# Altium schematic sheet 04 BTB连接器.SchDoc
size 420 x 297 mm
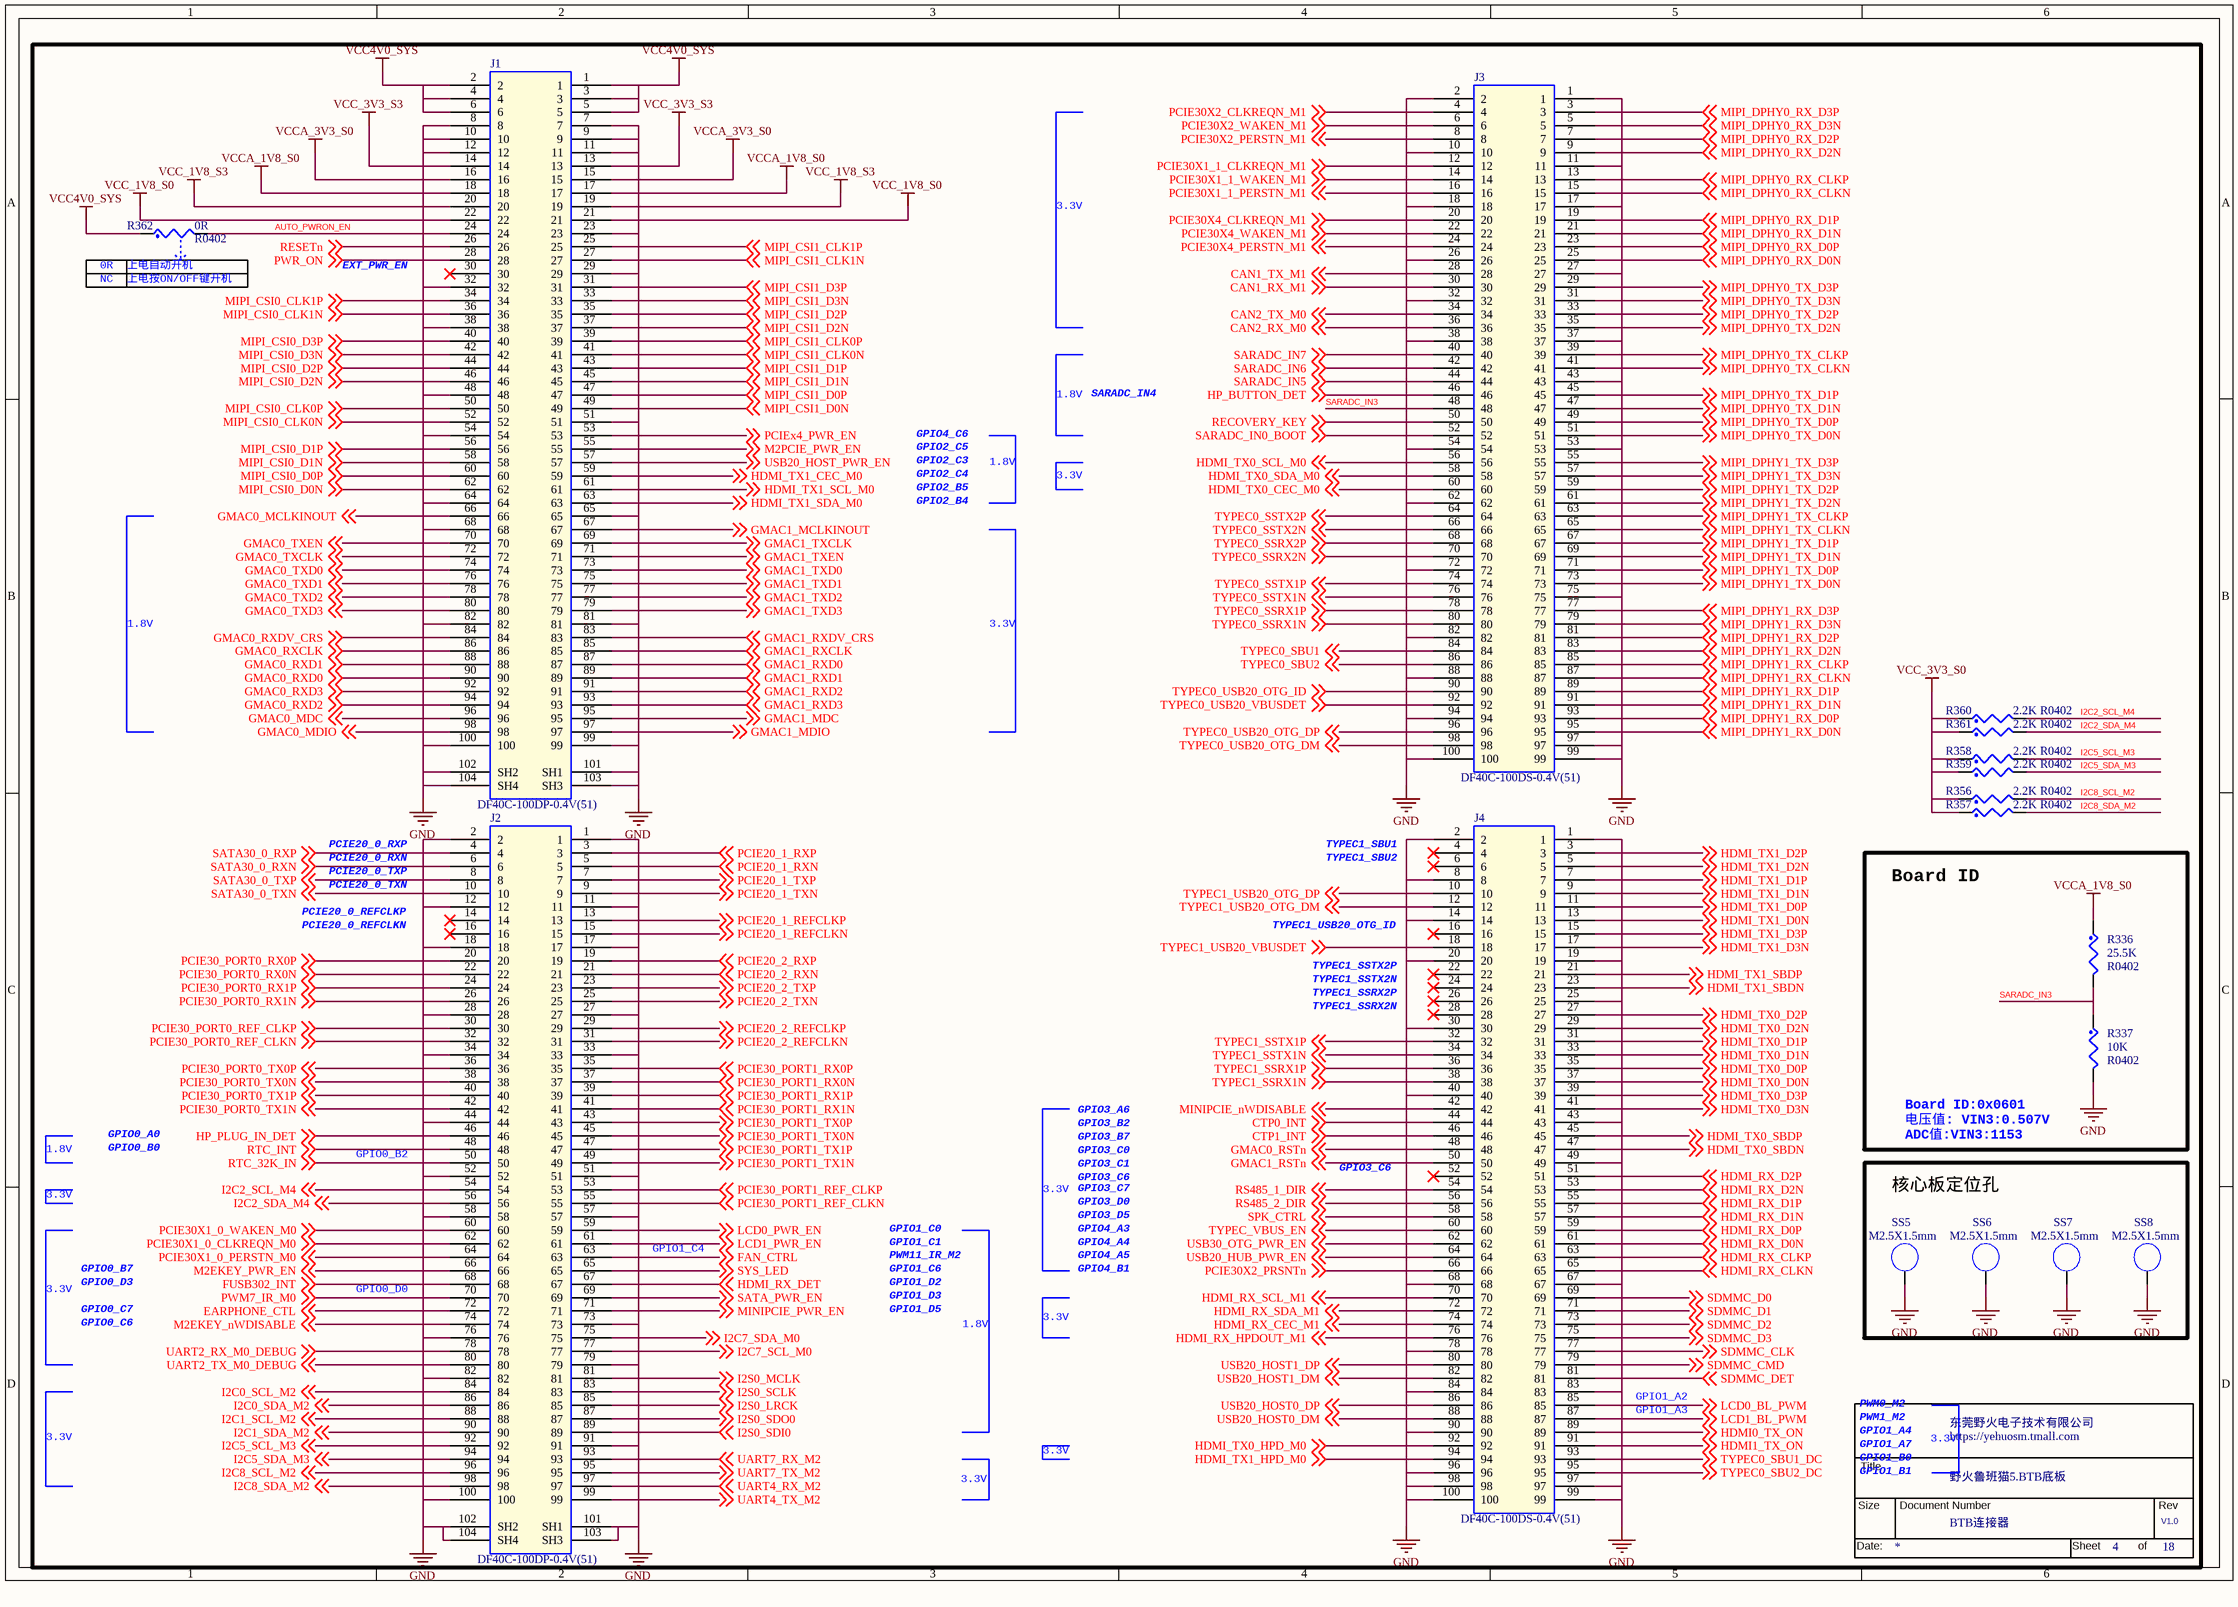
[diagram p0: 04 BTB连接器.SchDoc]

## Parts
*  Doc: BTB连接器  RevCode: V1.0  Title: 野火鲁班猫5.BTB底板  OrgName: 东莞野火电子技术有限公司  Page Number: 4  Page Count: 18  (hidden comment: TitleBlock_YHSCH)  (graphical)
J1  DF40C-100DP-0.4V(51)  [DF40C-100DP-0P4V]
J2  DF40C-100DP-0.4V(51)  [DF40C-100DP-0P4V]
J3  DF40C-100DS-0.4V(51)  [DF40HC-100DS-0P4V]
J4  DF40C-100DS-0.4V(51)  [DF40HC-100DS-0P4V]
R336  25.5K  [R0402]
R337  10K  [R0402]
R356  2.2K  [R0402]
R357  2.2K  [R0402]
R358  2.2K  [R0402]
R359  2.2K  [R0402]
R360  2.2K  [R0402]
R361  2.2K  [R0402]
R362  0R  [R0402]
SS5  M2.5X1.5mm  [SMTSO-M2r5]
SS6  M2.5X1.5mm  [SMTSO-M2r5]
SS7  M2.5X1.5mm  [SMTSO-M2r5]
SS8  M2.5X1.5mm  [SMTSO-M2r5]

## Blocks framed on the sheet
Board ID: R336 R337
核心板定位孔: SS5-SS8

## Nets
GND: J1.7 J1.8 J1.9 J1.10 J1.11 J1.12 J1.23 J1.29 J1.32 J1.38 J1.48 J1.51 J1.54 J1.64 J1.65 J1.68 J1.81 J1.82 J1.99 J1.100 J1.101(SH1) J1.102(SH2) J1.103(SH3) J1.104(SH4) J2.1 J2.2 J2.11 J2.12 J2.17 J2.18 J2.27 J2.28 J2.33 J2.34 J2.44 J2.51 J2.52 J2.57 J2.58 J2.73 J2.76 J2.79 J2.82 J2.91 J2.100 J2.101(SH1) J2.102(SH2) J2.103(SH3) J2.104(SH4) J3.1 J3.2 J3.10 J3.11 J3.17 J3.18 J3.26 J3.27 J3.32 J3.37 J3.38 J3.43 J3.53 J3.54 J3.62 J3.72 J3.75 J3.82 J3.88 J3.94 J3.97 J3.99 J3.100 J4.1 J4.2 J4.8 J4.14 J4.19 J4.20 J4.25 J4.30 J4.40 J4.43 J4.49 J4.67 J4.68 J4.78 J4.83 J4.84 J4.90 J4.96 J4.97 J4.98 J4.99 J4.100 R337.2 SS5.1(NC_1) SS6.1(NC_1) SS7.1(NC_1) SS8.1(NC_1)
VCC4V0_SYS: J1.1 J1.2 J1.3 J1.4 J1.5 J1.6 R362.1
VCC_1V8_S0: J1.21 J1.22
VCC_1V8_S3: J1.19 J1.20
VCC_3V3_S0: R356.1 R357.1 R358.1 R359.1 R360.1 R361.1
VCC_3V3_S3: J1.13 J1.14
VCCA_1V8_S0: J1.17 J1.18 R336.1
VCCA_3V3_S0: J1.15 J1.16
AUTO_PWRON_EN: J1.24 R362.2
CAN1_RX_M1: J3.30 ; off-sheet CAN1_RX_M1
CAN1_TX_M1: J3.28 ; off-sheet CAN1_TX_M1
CAN2_RX_M0: J3.36 ; off-sheet CAN2_RX_M0
CAN2_TX_M0: J3.34 ; off-sheet CAN2_TX_M0
CTP0_INT: J4.44 ; off-sheet CTP0_INT
CTP1_INT: J4.46 ; off-sheet CTP1_INT
EARPHONE_CTL: J2.72 ; off-sheet EARPHONE_CTL
FAN_CTRL: J2.63 ; off-sheet FAN_CTRL
FUSB302_INT: J2.68 ; off-sheet FUSB302_INT
GMAC0_MCLKINOUT: J1.66 ; off-sheet GMAC0_MCLKINOUT
GMAC0_MDC: J1.96 ; off-sheet GMAC0_MDC
GMAC0_MDIO: J1.98 ; off-sheet GMAC0_MDIO
GMAC0_RSTn: J4.48 ; off-sheet GMAC0_RSTn
GMAC0_RXCLK: J1.86 ; off-sheet GMAC0_RXCLK
GMAC0_RXD0: J1.90 ; off-sheet GMAC0_RXD0
GMAC0_RXD1: J1.88 ; off-sheet GMAC0_RXD1
GMAC0_RXD2: J1.94 ; off-sheet GMAC0_RXD2
GMAC0_RXD3: J1.92 ; off-sheet GMAC0_RXD3
GMAC0_RXDV_CRS: J1.84 ; off-sheet GMAC0_RXDV_CRS
GMAC0_TXCLK: J1.72 ; off-sheet GMAC0_TXCLK
GMAC0_TXD0: J1.74 ; off-sheet GMAC0_TXD0
GMAC0_TXD1: J1.76 ; off-sheet GMAC0_TXD1
GMAC0_TXD2: J1.78 ; off-sheet GMAC0_TXD2
GMAC0_TXD3: J1.80 ; off-sheet GMAC0_TXD3
GMAC0_TXEN: J1.70 ; off-sheet GMAC0_TXEN
GMAC1_MCLKINOUT: J1.67 ; off-sheet GMAC1_MCLKINOUT
GMAC1_MDC: J1.95 ; off-sheet GMAC1_MDC
GMAC1_MDIO: J1.97 ; off-sheet GMAC1_MDIO
GMAC1_RSTn: J4.50 ; off-sheet GMAC1_RSTn
GMAC1_RXCLK: J1.85 ; off-sheet GMAC1_RXCLK
GMAC1_RXD0: J1.87 ; off-sheet GMAC1_RXD0
GMAC1_RXD1: J1.89 ; off-sheet GMAC1_RXD1
GMAC1_RXD2: J1.91 ; off-sheet GMAC1_RXD2
GMAC1_RXD3: J1.93 ; off-sheet GMAC1_RXD3
GMAC1_RXDV_CRS: J1.83 ; off-sheet GMAC1_RXDV_CRS
GMAC1_TXCLK: J1.69 ; off-sheet GMAC1_TXCLK
GMAC1_TXD0: J1.73 ; off-sheet GMAC1_TXD0
GMAC1_TXD1: J1.75 ; off-sheet GMAC1_TXD1
GMAC1_TXD2: J1.77 ; off-sheet GMAC1_TXD2
GMAC1_TXD3: J1.79 ; off-sheet GMAC1_TXD3
GMAC1_TXEN: J1.71 ; off-sheet GMAC1_TXEN
HDMI0_TX_ON: J4.89 ; off-sheet HDMI0_TX_ON
HDMI1_TX_ON: J4.91 ; off-sheet HDMI1_TX_ON
HDMI_RX_CEC_M1: J4.74 ; off-sheet HDMI_RX_CEC_M1
HDMI_RX_CLKN: J4.65 ; off-sheet HDMI_RX_CLKN
HDMI_RX_CLKP: J4.63 ; off-sheet HDMI_RX_CLKP
HDMI_RX_D0N: J4.61 ; off-sheet HDMI_RX_D0N
HDMI_RX_D0P: J4.59 ; off-sheet HDMI_RX_D0P
HDMI_RX_D1N: J4.57 ; off-sheet HDMI_RX_D1N
HDMI_RX_D1P: J4.55 ; off-sheet HDMI_RX_D1P
HDMI_RX_D2N: J4.53 ; off-sheet HDMI_RX_D2N
HDMI_RX_D2P: J4.51 ; off-sheet HDMI_RX_D2P
HDMI_RX_DET: J2.67 ; off-sheet HDMI_RX_DET
HDMI_RX_HPDOUT_M1: J4.76 ; off-sheet HDMI_RX_HPDOUT_M1
HDMI_RX_SCL_M1: J4.70 ; off-sheet HDMI_RX_SCL_M1
HDMI_RX_SDA_M1: J4.72 ; off-sheet HDMI_RX_SDA_M1
HDMI_TX0_CEC_M0: J3.60 ; off-sheet HDMI_TX0_CEC_M0
HDMI_TX0_D0N: J4.37 ; off-sheet HDMI_TX0_D0N
HDMI_TX0_D0P: J4.35 ; off-sheet HDMI_TX0_D0P
HDMI_TX0_D1N: J4.33 ; off-sheet HDMI_TX0_D1N
HDMI_TX0_D1P: J4.31 ; off-sheet HDMI_TX0_D1P
HDMI_TX0_D2N: J4.29 ; off-sheet HDMI_TX0_D2N
HDMI_TX0_D2P: J4.27 ; off-sheet HDMI_TX0_D2P
HDMI_TX0_D3N: J4.41 ; off-sheet HDMI_TX0_D3N
HDMI_TX0_D3P: J4.39 ; off-sheet HDMI_TX0_D3P
HDMI_TX0_HPD_M0: J4.92 ; off-sheet HDMI_TX0_HPD_M0
HDMI_TX0_SBDN: J4.47 ; off-sheet HDMI_TX0_SBDN
HDMI_TX0_SBDP: J4.45 ; off-sheet HDMI_TX0_SBDP
HDMI_TX0_SCL_M0: J3.56 ; off-sheet HDMI_TX0_SCL_M0
HDMI_TX0_SDA_M0: J3.58 ; off-sheet HDMI_TX0_SDA_M0
HDMI_TX1_CEC_M0: J1.59 ; off-sheet HDMI_TX1_CEC_M0
HDMI_TX1_D0N: J4.13 ; off-sheet HDMI_TX1_D0N
HDMI_TX1_D0P: J4.11 ; off-sheet HDMI_TX1_D0P
HDMI_TX1_D1N: J4.9 ; off-sheet HDMI_TX1_D1N
HDMI_TX1_D1P: J4.7 ; off-sheet HDMI_TX1_D1P
HDMI_TX1_D2N: J4.5 ; off-sheet HDMI_TX1_D2N
HDMI_TX1_D2P: J4.3 ; off-sheet HDMI_TX1_D2P
HDMI_TX1_D3N: J4.17 ; off-sheet HDMI_TX1_D3N
HDMI_TX1_D3P: J4.15 ; off-sheet HDMI_TX1_D3P
HDMI_TX1_HPD_M0: J4.94 ; off-sheet HDMI_TX1_HPD_M0
HDMI_TX1_SBDN: J4.23 ; off-sheet HDMI_TX1_SBDN
HDMI_TX1_SBDP: J4.21 ; off-sheet HDMI_TX1_SBDP
HDMI_TX1_SCL_M0: J1.61 ; off-sheet HDMI_TX1_SCL_M0
HDMI_TX1_SDA_M0: J1.63 ; off-sheet HDMI_TX1_SDA_M0
HP_BUTTON_DET: J3.46 ; off-sheet HP_BUTTON_DET
HP_PLUG_IN_DET: J2.46 ; off-sheet HP_PLUG_IN_DET
I2C0_SCL_M2: J2.84 ; off-sheet I2C0_SCL_M2
I2C0_SDA_M2: J2.86 ; off-sheet I2C0_SDA_M2
I2C1_SCL_M2: J2.88 ; off-sheet I2C1_SCL_M2
I2C1_SDA_M2: J2.90 ; off-sheet I2C1_SDA_M2
I2C2_SCL_M4: J2.54 R360.2 ; off-sheet I2C2_SCL_M4
I2C2_SDA_M4: J2.56 R361.2 ; off-sheet I2C2_SDA_M4
I2C5_SCL_M3: J2.92 R358.2 ; off-sheet I2C5_SCL_M3
I2C5_SDA_M3: J2.94 R359.2 ; off-sheet I2C5_SDA_M3
I2C7_SCL_M0: J2.77 ; off-sheet I2C7_SCL_M0
I2C7_SDA_M0: J2.75 ; off-sheet I2C7_SDA_M0
I2C8_SCL_M2: J2.96 R356.2 ; off-sheet I2C8_SCL_M2
I2C8_SDA_M2: J2.98 R357.2 ; off-sheet I2C8_SDA_M2
I2S0_LRCK: J2.85 ; off-sheet I2S0_LRCK
I2S0_MCLK: J2.81 ; off-sheet I2S0_MCLK
I2S0_SCLK: J2.83 ; off-sheet I2S0_SCLK
I2S0_SDI0: J2.89 ; off-sheet I2S0_SDI0
I2S0_SDO0: J2.87 ; off-sheet I2S0_SDO0
LCD0_BL_PWM: J4.85 ; off-sheet LCD0_BL_PWM
LCD0_PWR_EN: J2.59 ; off-sheet LCD0_PWR_EN
LCD1_BL_PWM: J4.87 ; off-sheet LCD1_BL_PWM
LCD1_PWR_EN: J2.61 ; off-sheet LCD1_PWR_EN
M2EKEY_nWDISABLE: J2.74 ; off-sheet M2EKEY_nWDISABLE
M2EKEY_PWR_EN: J2.66 ; off-sheet M2EKEY_PWR_EN
M2PCIE_PWR_EN: J1.55 ; off-sheet M2PCIE_PWR_EN
MINIPCIE_nWDISABLE: J4.42 ; off-sheet MINIPCIE_nWDISABLE
MINIPCIE_PWR_EN: J2.71 ; off-sheet MINIPCIE_PWR_EN
MIPI_CSI0_CLK0N: J1.52 ; off-sheet MIPI_CSI0_CLK0N
MIPI_CSI0_CLK0P: J1.50 ; off-sheet MIPI_CSI0_CLK0P
MIPI_CSI0_CLK1N: J1.36 ; off-sheet MIPI_CSI0_CLK1N
MIPI_CSI0_CLK1P: J1.34 ; off-sheet MIPI_CSI0_CLK1P
MIPI_CSI0_D0N: J1.62 ; off-sheet MIPI_CSI0_D0N
MIPI_CSI0_D0P: J1.60 ; off-sheet MIPI_CSI0_D0P
MIPI_CSI0_D1N: J1.58 ; off-sheet MIPI_CSI0_D1N
MIPI_CSI0_D1P: J1.56 ; off-sheet MIPI_CSI0_D1P
MIPI_CSI0_D2N: J1.46 ; off-sheet MIPI_CSI0_D2N
MIPI_CSI0_D2P: J1.44 ; off-sheet MIPI_CSI0_D2P
MIPI_CSI0_D3N: J1.42 ; off-sheet MIPI_CSI0_D3N
MIPI_CSI0_D3P: J1.40 ; off-sheet MIPI_CSI0_D3P
MIPI_CSI1_CLK0N: J1.41 ; off-sheet MIPI_CSI1_CLK0N
MIPI_CSI1_CLK0P: J1.39 ; off-sheet MIPI_CSI1_CLK0P
MIPI_CSI1_CLK1N: J1.27 ; off-sheet MIPI_CSI1_CLK1N
MIPI_CSI1_CLK1P: J1.25 ; off-sheet MIPI_CSI1_CLK1P
MIPI_CSI1_D0N: J1.49 ; off-sheet MIPI_CSI1_D0N
MIPI_CSI1_D0P: J1.47 ; off-sheet MIPI_CSI1_D0P
MIPI_CSI1_D1N: J1.45 ; off-sheet MIPI_CSI1_D1N
MIPI_CSI1_D1P: J1.43 ; off-sheet MIPI_CSI1_D1P
MIPI_CSI1_D2N: J1.37 ; off-sheet MIPI_CSI1_D2N
MIPI_CSI1_D2P: J1.35 ; off-sheet MIPI_CSI1_D2P
MIPI_CSI1_D3N: J1.33 ; off-sheet MIPI_CSI1_D3N
MIPI_CSI1_D3P: J1.31 ; off-sheet MIPI_CSI1_D3P
MIPI_DPHY0_RX_CLKN: J3.15 ; off-sheet MIPI_DPHY0_RX_CLKN
MIPI_DPHY0_RX_CLKP: J3.13 ; off-sheet MIPI_DPHY0_RX_CLKP
MIPI_DPHY0_RX_D0N: J3.25 ; off-sheet MIPI_DPHY0_RX_D0N
MIPI_DPHY0_RX_D0P: J3.23 ; off-sheet MIPI_DPHY0_RX_D0P
MIPI_DPHY0_RX_D1N: J3.21 ; off-sheet MIPI_DPHY0_RX_D1N
MIPI_DPHY0_RX_D1P: J3.19 ; off-sheet MIPI_DPHY0_RX_D1P
MIPI_DPHY0_RX_D2N: J3.9 ; off-sheet MIPI_DPHY0_RX_D2N
MIPI_DPHY0_RX_D2P: J3.7 ; off-sheet MIPI_DPHY0_RX_D2P
MIPI_DPHY0_RX_D3N: J3.5 ; off-sheet MIPI_DPHY0_RX_D3N
MIPI_DPHY0_RX_D3P: J3.3 ; off-sheet MIPI_DPHY0_RX_D3P
MIPI_DPHY0_TX_CLKN: J3.41 ; off-sheet MIPI_DPHY0_TX_CLKN
MIPI_DPHY0_TX_CLKP: J3.39 ; off-sheet MIPI_DPHY0_TX_CLKP
MIPI_DPHY0_TX_D0N: J3.51 ; off-sheet MIPI_DPHY0_TX_D0N
MIPI_DPHY0_TX_D0P: J3.49 ; off-sheet MIPI_DPHY0_TX_D0P
MIPI_DPHY0_TX_D1N: J3.47 ; off-sheet MIPI_DPHY0_TX_D1N
MIPI_DPHY0_TX_D1P: J3.45 ; off-sheet MIPI_DPHY0_TX_D1P
MIPI_DPHY0_TX_D2N: J3.35 ; off-sheet MIPI_DPHY0_TX_D2N
MIPI_DPHY0_TX_D2P: J3.33 ; off-sheet MIPI_DPHY0_TX_D2P
MIPI_DPHY0_TX_D3N: J3.31 ; off-sheet MIPI_DPHY0_TX_D3N
MIPI_DPHY0_TX_D3P: J3.29 ; off-sheet MIPI_DPHY0_TX_D3P
MIPI_DPHY1_RX_CLKN: J3.87 ; off-sheet MIPI_DPHY1_RX_CLKN
MIPI_DPHY1_RX_CLKP: J3.85 ; off-sheet MIPI_DPHY1_RX_CLKP
MIPI_DPHY1_RX_D0N: J3.95 ; off-sheet MIPI_DPHY1_RX_D0N
MIPI_DPHY1_RX_D0P: J3.93 ; off-sheet MIPI_DPHY1_RX_D0P
MIPI_DPHY1_RX_D1N: J3.91 ; off-sheet MIPI_DPHY1_RX_D1N
MIPI_DPHY1_RX_D1P: J3.89 ; off-sheet MIPI_DPHY1_RX_D1P
MIPI_DPHY1_RX_D2N: J3.83 ; off-sheet MIPI_DPHY1_RX_D2N
MIPI_DPHY1_RX_D2P: J3.81 ; off-sheet MIPI_DPHY1_RX_D2P
MIPI_DPHY1_RX_D3N: J3.79 ; off-sheet MIPI_DPHY1_RX_D3N
MIPI_DPHY1_RX_D3P: J3.77 ; off-sheet MIPI_DPHY1_RX_D3P
MIPI_DPHY1_TX_CLKN: J3.65 ; off-sheet MIPI_DPHY1_TX_CLKN
MIPI_DPHY1_TX_CLKP: J3.63 ; off-sheet MIPI_DPHY1_TX_CLKP
MIPI_DPHY1_TX_D0N: J3.73 ; off-sheet MIPI_DPHY1_TX_D0N
MIPI_DPHY1_TX_D0P: J3.71 ; off-sheet MIPI_DPHY1_TX_D0P
MIPI_DPHY1_TX_D1N: J3.69 ; off-sheet MIPI_DPHY1_TX_D1N
MIPI_DPHY1_TX_D1P: J3.67 ; off-sheet MIPI_DPHY1_TX_D1P
MIPI_DPHY1_TX_D2N: J3.61 ; off-sheet MIPI_DPHY1_TX_D2N
MIPI_DPHY1_TX_D2P: J3.59 ; off-sheet MIPI_DPHY1_TX_D2P
MIPI_DPHY1_TX_D3N: J3.57 ; off-sheet MIPI_DPHY1_TX_D3N
MIPI_DPHY1_TX_D3P: J3.55 ; off-sheet MIPI_DPHY1_TX_D3P
PCIE20_1_REFCLKN: J2.15 ; off-sheet PCIE20_1_REFCLKN
PCIE20_1_REFCLKP: J2.13 ; off-sheet PCIE20_1_REFCLKP
PCIE20_1_RXN: J2.5 ; off-sheet PCIE20_1_RXN
PCIE20_1_RXP: J2.3 ; off-sheet PCIE20_1_RXP
PCIE20_1_TXN: J2.9 ; off-sheet PCIE20_1_TXN
PCIE20_1_TXP: J2.7 ; off-sheet PCIE20_1_TXP
PCIE20_2_REFCLKN: J2.31 ; off-sheet PCIE20_2_REFCLKN
PCIE20_2_REFCLKP: J2.29 ; off-sheet PCIE20_2_REFCLKP
PCIE20_2_RXN: J2.21 ; off-sheet PCIE20_2_RXN
PCIE20_2_RXP: J2.19 ; off-sheet PCIE20_2_RXP
PCIE20_2_TXN: J2.25 ; off-sheet PCIE20_2_TXN
PCIE20_2_TXP: J2.23 ; off-sheet PCIE20_2_TXP
PCIE30_PORT0_REF_CLKN: J2.32 ; off-sheet PCIE30_PORT0_REF_CLKN
PCIE30_PORT0_REF_CLKP: J2.30 ; off-sheet PCIE30_PORT0_REF_CLKP
PCIE30_PORT0_RX0N: J2.22 ; off-sheet PCIE30_PORT0_RX0N
PCIE30_PORT0_RX0P: J2.20 ; off-sheet PCIE30_PORT0_RX0P
PCIE30_PORT0_RX1N: J2.26 ; off-sheet PCIE30_PORT0_RX1N
PCIE30_PORT0_RX1P: J2.24 ; off-sheet PCIE30_PORT0_RX1P
PCIE30_PORT0_TX0N: J2.38 ; off-sheet PCIE30_PORT0_TX0N
PCIE30_PORT0_TX0P: J2.36 ; off-sheet PCIE30_PORT0_TX0P
PCIE30_PORT0_TX1N: J2.42 ; off-sheet PCIE30_PORT0_TX1N
PCIE30_PORT0_TX1P: J2.40 ; off-sheet PCIE30_PORT0_TX1P
PCIE30_PORT1_REF_CLKN: J2.55 ; off-sheet PCIE30_PORT1_REF_CLKN
PCIE30_PORT1_REF_CLKP: J2.53 ; off-sheet PCIE30_PORT1_REF_CLKP
PCIE30_PORT1_RX0N: J2.37 ; off-sheet PCIE30_PORT1_RX0N
PCIE30_PORT1_RX0P: J2.35 ; off-sheet PCIE30_PORT1_RX0P
PCIE30_PORT1_RX1N: J2.41 ; off-sheet PCIE30_PORT1_RX1N
PCIE30_PORT1_RX1P: J2.39 ; off-sheet PCIE30_PORT1_RX1P
PCIE30_PORT1_TX0N: J2.45 ; off-sheet PCIE30_PORT1_TX0N
PCIE30_PORT1_TX0P: J2.43 ; off-sheet PCIE30_PORT1_TX0P
PCIE30_PORT1_TX1N: J2.49 ; off-sheet PCIE30_PORT1_TX1N
PCIE30_PORT1_TX1P: J2.47 ; off-sheet PCIE30_PORT1_TX1P
PCIE30X1_0_CLKREQN_M0: J2.62 ; off-sheet PCIE30X1_0_CLKREQN_M0
PCIE30X1_0_PERSTN_M0: J2.64 ; off-sheet PCIE30X1_0_PERSTN_M0
PCIE30X1_0_WAKEN_M0: J2.60 ; off-sheet PCIE30X1_0_WAKEN_M0
PCIE30X1_1_CLKREQN_M1: J3.12 ; off-sheet PCIE30X1_1_CLKREQN_M1
PCIE30X1_1_PERSTN_M1: J3.16 ; off-sheet PCIE30X1_1_PERSTN_M1
PCIE30X1_1_WAKEN_M1: J3.14 ; off-sheet PCIE30X1_1_WAKEN_M1
PCIE30X2_CLKREQN_M1: J3.4 ; off-sheet PCIE30X2_CLKREQN_M1
PCIE30X2_PERSTN_M1: J3.8 ; off-sheet PCIE30X2_PERSTN_M1
PCIE30X2_PRSNTn: J4.66 ; off-sheet PCIE30X2_PRSNTn
PCIE30X2_WAKEN_M1: J3.6 ; off-sheet PCIE30X2_WAKEN_M1
PCIE30X4_CLKREQN_M1: J3.20 ; off-sheet PCIE30X4_CLKREQN_M1
PCIE30X4_PERSTN_M1: J3.24 ; off-sheet PCIE30X4_PERSTN_M1
PCIE30X4_WAKEN_M1: J3.22 ; off-sheet PCIE30X4_WAKEN_M1
PCIEx4_PWR_EN: J1.53 ; off-sheet PCIEx4_PWR_EN
PWM7_IR_M0: J2.70 ; off-sheet PWM7_IR_M0
PWR_ON: J1.28 ; off-sheet PWR_ON
RECOVERY_KEY: J3.50 ; off-sheet RECOVERY_KEY
RESETn: J1.26 ; off-sheet RESETn
RS485_1_DIR: J4.54 ; off-sheet RS485_1_DIR
RS485_2_DIR: J4.56 ; off-sheet RS485_2_DIR
RTC_32K_IN: J2.50 ; off-sheet RTC_32K_IN
RTC_INT: J2.48 ; off-sheet RTC_INT
SARADC_IN0_BOOT: J3.52 ; off-sheet SARADC_IN0_BOOT
SARADC_IN3: J3.48 R336.2 R337.1
SARADC_IN5: J3.44 ; off-sheet SARADC_IN5
SARADC_IN6: J3.42 ; off-sheet SARADC_IN6
SARADC_IN7: J3.40 ; off-sheet SARADC_IN7
SATA30_0_RXN: J2.6 ; off-sheet SATA30_0_RXN
SATA30_0_RXP: J2.4 ; off-sheet SATA30_0_RXP
SATA30_0_TXN: J2.10 ; off-sheet SATA30_0_TXN
SATA30_0_TXP: J2.8 ; off-sheet SATA30_0_TXP
SATA_PWR_EN: J2.69 ; off-sheet SATA_PWR_EN
SDMMC_CLK: J4.77 ; off-sheet SDMMC_CLK
SDMMC_CMD: J4.79 ; off-sheet SDMMC_CMD
SDMMC_D0: J4.69 ; off-sheet SDMMC_D0
SDMMC_D1: J4.71 ; off-sheet SDMMC_D1
SDMMC_D2: J4.73 ; off-sheet SDMMC_D2
SDMMC_D3: J4.75 ; off-sheet SDMMC_D3
SDMMC_DET: J4.81 ; off-sheet SDMMC_DET
SPK_CTRL: J4.58 ; off-sheet SPK_CTRL
SYS_LED: J2.65 ; off-sheet SYS_LED
TYPEC0_SBU1: J3.84 ; off-sheet TYPEC0_SBU1
TYPEC0_SBU1_DC: J4.93 ; off-sheet TYPEC0_SBU1_DC
TYPEC0_SBU2: J3.86 ; off-sheet TYPEC0_SBU2
TYPEC0_SBU2_DC: J4.95 ; off-sheet TYPEC0_SBU2_DC
TYPEC0_SSRX1N: J3.80 ; off-sheet TYPEC0_SSRX1N
TYPEC0_SSRX1P: J3.78 ; off-sheet TYPEC0_SSRX1P
TYPEC0_SSRX2N: J3.70 ; off-sheet TYPEC0_SSRX2N
TYPEC0_SSRX2P: J3.68 ; off-sheet TYPEC0_SSRX2P
TYPEC0_SSTX1N: J3.76 ; off-sheet TYPEC0_SSTX1N
TYPEC0_SSTX1P: J3.74 ; off-sheet TYPEC0_SSTX1P
TYPEC0_SSTX2N: J3.66 ; off-sheet TYPEC0_SSTX2N
TYPEC0_SSTX2P: J3.64 ; off-sheet TYPEC0_SSTX2P
TYPEC0_USB20_OTG_DM: J3.98 ; off-sheet TYPEC0_USB20_OTG_DM
TYPEC0_USB20_OTG_DP: J3.96 ; off-sheet TYPEC0_USB20_OTG_DP
TYPEC0_USB20_OTG_ID: J3.90 ; off-sheet TYPEC0_USB20_OTG_ID
TYPEC0_USB20_VBUSDET: J3.92 ; off-sheet TYPEC0_USB20_VBUSDET
TYPEC1_SSRX1N: J4.38 ; off-sheet TYPEC1_SSRX1N
TYPEC1_SSRX1P: J4.36 ; off-sheet TYPEC1_SSRX1P
TYPEC1_SSTX1N: J4.34 ; off-sheet TYPEC1_SSTX1N
TYPEC1_SSTX1P: J4.32 ; off-sheet TYPEC1_SSTX1P
TYPEC1_USB20_OTG_DM: J4.12 ; off-sheet TYPEC1_USB20_OTG_DM
TYPEC1_USB20_OTG_DP: J4.10 ; off-sheet TYPEC1_USB20_OTG_DP
TYPEC1_USB20_VBUSDET: J4.18 ; off-sheet TYPEC1_USB20_VBUSDET
TYPEC_VBUS_EN: J4.60 ; off-sheet TYPEC_VBUS_EN
UART2_RX_M0_DEBUG: J2.78 ; off-sheet UART2_RX_M0_DEBUG
UART2_TX_M0_DEBUG: J2.80 ; off-sheet UART2_TX_M0_DEBUG
UART4_RX_M2: J2.97 ; off-sheet UART4_RX_M2
UART4_TX_M2: J2.99 ; off-sheet UART4_TX_M2
UART7_RX_M2: J2.93 ; off-sheet UART7_RX_M2
UART7_TX_M2: J2.95 ; off-sheet UART7_TX_M2
USB20_HOST0_DM: J4.88 ; off-sheet USB20_HOST0_DM
USB20_HOST0_DP: J4.86 ; off-sheet USB20_HOST0_DP
USB20_HOST1_DM: J4.82 ; off-sheet USB20_HOST1_DM
USB20_HOST1_DP: J4.80 ; off-sheet USB20_HOST1_DP
USB20_HOST_PWR_EN: J1.57 ; off-sheet USB20_HOST_PWR_EN
USB20_HUB_PWR_EN: J4.64 ; off-sheet USB20_HUB_PWR_EN
USB30_OTG_PWR_EN: J4.62 ; off-sheet USB30_OTG_PWR_EN

Not connected (* = marked no-connect by the designer): J1 30*; J2 14* 16*; J4 4* 6* 16* 22* 24* 26* 28* 52*

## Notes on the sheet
- 3.3V
- (near R362) 0R
- NC
- (near R362) 上电自动开机
- (near R362) 上电按ON/OFF键开机
- EXT_PWR_EN
- 1.8V
- SARADC_IN4
- GPIO4_C6
- GPIO2_C5
- GPIO2_C3
- GPIO2_C4
- GPIO2_B5
- GPIO2_B4
- PCIE20_0_RXP
- PCIE20_0_RXN
- TYPEC1_SBU1
- TYPEC1_SBU2
- PCIE20_0_REFCLKP
- PCIE20_0_REFCLKN
- PCIE20_0_TXP
- PCIE20_0_TXN
- TYPEC1_USB20_OTG_ID
- TYPEC1_SSRX2P
- TYPEC1_SSTX2P
- TYPEC1_SSTX2N
- TYPEC1_SSRX2N
- GPIO0_A0
- GPIO3_A6
- GPIO3_B2
- (near R337) Board ID:0x0601
  电压值: VIN3:0.507V
  ADC值:VIN3:1153
- GPIO0_B0
- GPIO0_B2
- GPIO3_B7
- GPIO3_C0
- GPIO3_C1
- GPIO3_C7
- GPIO3_D0
- GPIO3_C6
- GPIO0_B7
- GPIO1_C4
- GPIO1_C0
- GPIO1_C1
- PWM11_IR_M2
- GPIO1_C6
- GPIO3_D5
- GPIO4_A3
- GPIO4_A4
- GPIO4_A5
- GPIO4_B1
- GPIO0_D3
- GPIO0_C7
- GPIO0_C6
- GPIO0_D0
- GPIO1_D3
- GPIO1_D2
- GPIO1_D5
- GPIO1_A2
- (near *) PWM0_M2
- GPIO1_A3
- (near *) PWM1_M2
- (near *) GPIO1_A4
- (near *) GPIO1_A7
- (near *) GPIO1_B0
- GPIO1_B1

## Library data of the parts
* = TitleBlock_YHSCH: Cage Code: 1
J1 = DF40C-100DP: 备注: 鲁班猫cm4; 生命周期: 量产; 价格: 3.39; 规格书: 广濑-DF40_Catalog.pdf; 类别: BTB连接器; 品牌: 广濑; 条码: EBFCIS231113172457; 规格: 0.4mm BTB公座2*50P 双槽 立贴式 高度1.14mm
J2 = DF40C-100DP: 规格: 0.4mm BTB公座2*50P 双槽 立贴式 高度1.14mm; 条码: EBFCIS231113172457; 品牌: 广濑; 类别: BTB连接器; 规格书: 广濑-DF40_Catalog.pdf; 价格: 3.39; 生命周期: 量产; 备注: 鲁班猫cm4
J3 J4 = SGDBM-05-100P-H10: 备注: 鲁班猫cm4; 生命周期: 量产; 价格: 3.93; 规格书: 广濑-DF40_Catalog.pdf; 类别: BTB连接器; 品牌: 广濑; 条码: EBFCIS231113172912; 规格: 0.4mm BTB母座2*50P 双槽 立贴式 合高1.5mm
R336 = RES: CLASS: DISCRETE; 规格: 贴片电阻25.5K 1% 1/16W 0402; 规格编号: CQ02WGF2552TCE; 条码: EBF29070291; 品牌: 厚声; 类别: 贴片电阻0402; 规格书: 厚声-无铅厚膜电阻.pdf; 价格: 0.006152; 生命周期: 量产
R337 = RES: CLASS: DISCRETE; 规格: 贴片电阻10K 1% 1/16W 0402; 规格编号: 0402WGF1002TCE; 条码: EBF29070046; 品牌: 厚声; 类别: 贴片电阻0402; 规格书: 厚声-无铅厚膜电阻.pdf; 价格: 0.002773; 生命周期: 量产
R356-R361 = RES: CLASS: DISCRETE; 生命周期: 量产; 规格书: 合科泰-RI系列电阻.pdf; 类别: 贴片电阻0402; 品牌: 合科泰; 条码: EBF29070051; 规格编号: RI0402L2201FT; 规格: 贴片电阻2.2K 1% 1/16W 0402
R362 = RES: CLASS: DISCRETE; 规格: 贴片电阻0R 1% 1/16W 0402; 规格编号: RI0402L000FT; 条码: EBF29070049; 品牌: 合科泰; 类别: 贴片电阻0402; 规格书: 合科泰-RI系列电阻.pdf; 生命周期: 量产
SS5 SS7 = SPACER: CLASS: IC; 备注: 通用; 生命周期: 量产; 规格书: 雄和远景_SMTSO2530CTJ.pdf; 类别: 贴片螺母; 品牌: 雄和远景; 条码: EBFCIS240816170946; 规格编号: SMTSO2515CTJ; 规格: SMT贴片螺母M2.5 台阶高度1.4MM 台阶外径：4.09MM 螺柱长度：1.5MM
SS6 SS8 = SPACER: CLASS: IC; 规格: SMT贴片螺母M2.5 台阶高度1.4MM 台阶外径：4.09MM 螺柱长度：1.5MM; 规格编号: SMTSO2515CTJ; 条码: EBFCIS240816170946; 品牌: 雄和远景; 类别: 贴片螺母; 规格书: 雄和远景_SMTSO2530CTJ.pdf; 生命周期: 量产; 备注: 通用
